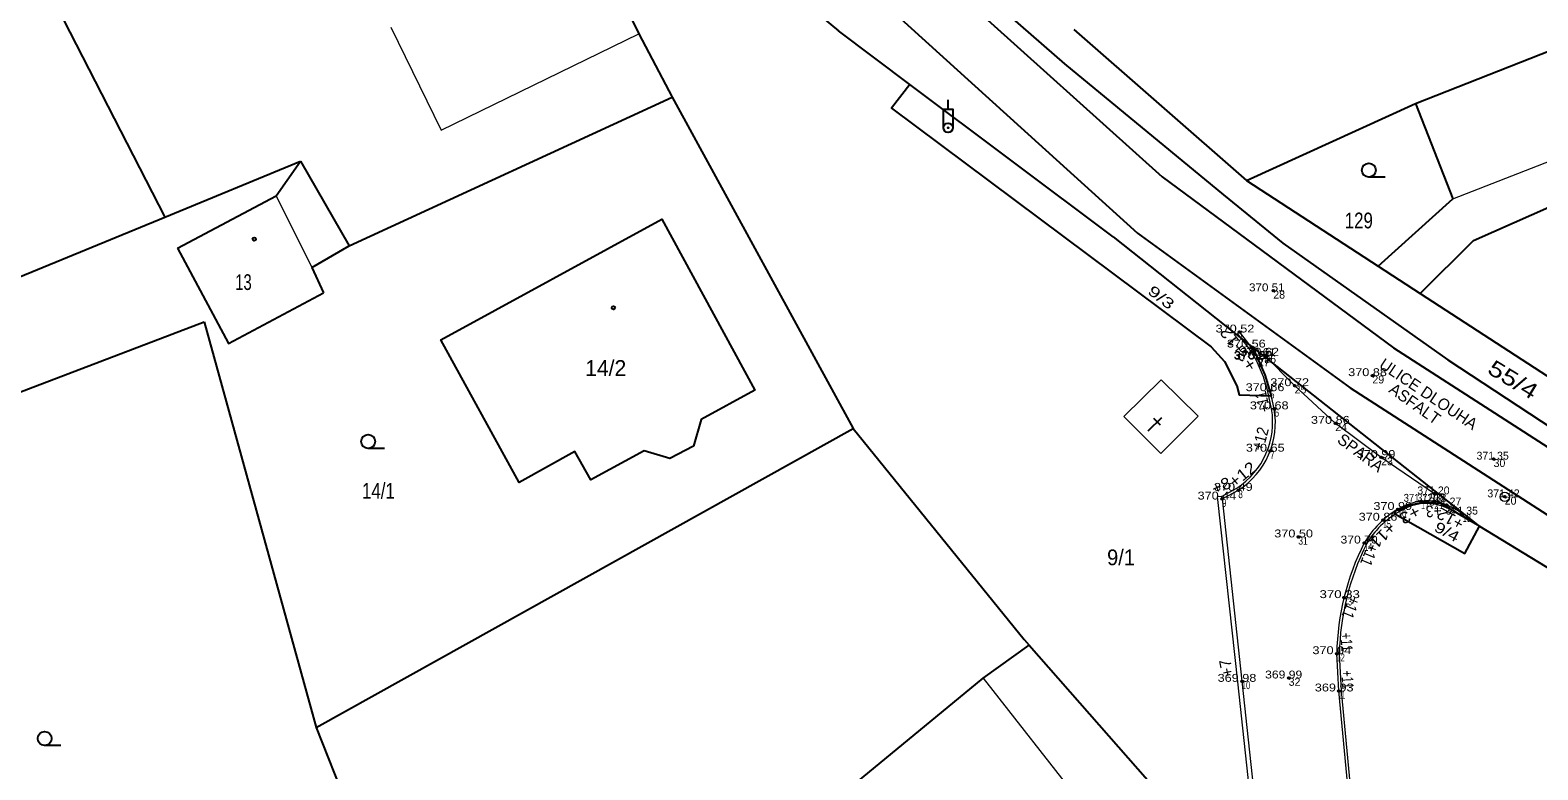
# Model space of a CAD drawing. Extents: x -592965 to -592390, y -1145071 to -1144631.
# Drawn here: x -592701.3 to -592620.1, y -1144793.9 to -1144754 of the extents above; entities that cross this region are included whole.
import ezdxf
from ezdxf.enums import TextEntityAlignment as Align

# ---------------------------------------------------------------- set-up
doc = ezdxf.new("R2010")
doc.units = 0
doc.header["$LTSCALE"] = 0.17
doc.header["$PDMODE"] = 32
doc.header["$PDSIZE"] = 0.085
for name, color, linetype, lineweight in [('1', 7, 'Continuous', 13), ('3', 7, 'Continuous', 13), ('4', 7, 'Continuous', 25)]:
    doc.layers.add(name, color=color, linetype=linetype, lineweight=lineweight)
doc.layers.add('2', color=7, linetype='Continuous')

msp = doc.modelspace()

# ---------------------------------------------------------------- linework, layer by layer
at = {"layer": '1'}
for p, q in [((-592635.5, -1144771.07), (-592636.13, -1144770.26)), ((-592635.61, -1144771.15), (-592635.5, -1144771.07)), ((-592634.48, -1144773.42), (-592634.61, -1144773.46)), ((-592634.4, -1144774.41), (-592634.61, -1144773.46)), ((-592634.26, -1144774.4), (-592634.48, -1144773.42)), ((-592634.26, -1144774.4), (-592634.4, -1144774.41)), ((-592637.09, -1144779.12), (-592637.33, -1144779.15)), ((-592637.33, -1144779.15), (-592637.31, -1144779.29)), ((-592637.07, -1144779.26), (-592636.19, -1144778.79)), ((-592627.6, -1144779.82), (-592627.53, -1144779.95)), ((-592624.97, -1144779.58), (-592625.03, -1144779.71)), ((-592628.4, -1144780.4), (-592628.3, -1144780.5)), ((-592624.1, -1144780.07), (-592624.18, -1144780.18))]:
    msp.add_line(p, q, dxfattribs=at)
for points in [[(-592635.43, -1144771.44), (-592635.61, -1144771.15), (-592636.24, -1144770.35), (-592636.13, -1144770.26)], [(-592625.64, -1144779.38), (-592625.62, -1144778.98), (-592628.5, -1144777.02), (-592630.97, -1144775.18), (-592633.16, -1144773.15), (-592634.79, -1144771.51), (-592635.14, -1144771.68)], [(-592637.07, -1144779.26), (-592637.09, -1144779.12), (-592636.28, -1144778.68)], [(-592637.31, -1144779.29), (-592636.24, -1144789.11), (-592635.14, -1144799.25)], [(-592637.07, -1144779.26), (-592636, -1144789.08), (-592634.9, -1144799.22)], [(-592629.52, -1144802.71), (-592629.9, -1144798.92), (-592630.78, -1144789.6), (-592630.89, -1144787.59)], [(-592629.38, -1144802.7), (-592629.76, -1144798.91), (-592630.64, -1144789.59), (-592630.75, -1144787.6)]]:
    msp.add_lwpolyline(points, dxfattribs=at)
msp.add_circle((-592621.84, -1144779.14), 0.25, dxfattribs=at)
for centre, radius, start, end in [((-592640.1575, -1144774.2299), 5.6283, 26.93992, 34.15522), ((-592641.5166, -1144775.0872), 7.0957, 13.25738, 30.93109), ((-592643.1786, -1144775.7243), 8.9986, 14.83708, 26.70742), ((-592638.6054, -1144775.1073), 4.2628, 303.05919, 9.41484), ((-592638.5399, -1144775.1376), 4.343, 302.75725, 9.77875), ((-592625.0473, -1144784.1827), 5.0547, 120.33284, 149.66716), ((-592625.1307, -1144784.1231), 4.8137, 119.89707, 149.77646), ((-592625.995, -1144782.3841), 3.025, 83.26049, 122.04462), ((-592625.995, -1144782.3443), 2.8441, 83.23556, 122.66415), ((-592626.4518, -1144783.285), 3.8474, 53.80834, 78.12308), ((-592626.3924, -1144783.1229), 3.8178, 53.09689, 78.6334), ((-592617.2255, -1144787.8194), 13.6664, 153.07049, 179.03805), ((-592617.083, -1144787.8514), 13.6693, 153.25553, 178.94635)]:
    msp.add_arc(centre, radius, start, end, dxfattribs=at)
at = {"layer": '2'}
for p in [(-592634.31, -1144768.04), (-592636.13, -1144770.26), (-592635.5, -1144771.07), (-592635.14, -1144771.68), (-592635.12, -1144771.72), (-592634.79, -1144771.51), (-592634.78, -1144771.53), (-592628.97, -1144772.61), (-592634.48, -1144773.42), (-592633.16, -1144773.15), (-592634.26, -1144774.4), (-592630.97, -1144775.18), (-592634.48, -1144776.68), (-592628.5, -1144777.02), (-592622.44, -1144777.11), (-592637.07, -1144779.26), (-592636.19, -1144778.79), (-592625.62, -1144778.98), (-592621.84, -1144779.14), (-592627.6, -1144779.82), (-592626.35, -1144779.38), (-592625.64, -1144779.38), (-592624.97, -1144779.58), (-592624.1, -1144780.07), (-592628.4, -1144780.4), (-592632.96, -1144781.3), (-592629.41, -1144781.63), (-592630.5, -1144784.57), (-592630.89, -1144787.59), (-592633.48, -1144788.9), (-592636, -1144789.08), (-592630.78, -1144789.6)]:
    msp.add_point(p, dxfattribs=at)
at = {"layer": '3'}
for centre, radius in [((-592634.3101, -1144768.0399), 0.0625), ((-592634.3101, -1144768.0399), 0.0395), ((-592634.3101, -1144768.0399), 0.0125), ((-592636.1301, -1144770.2599), 0.0625), ((-592636.1301, -1144770.2599), 0.0395), ((-592636.1301, -1144770.2599), 0.0125), ((-592635.5001, -1144771.0699), 0.0625), ((-592635.5001, -1144771.0699), 0.0395), ((-592635.5001, -1144771.0699), 0.0125), ((-592635.1401, -1144771.6799), 0.0625), ((-592635.1201, -1144771.7199), 0.0625), ((-592635.1401, -1144771.6799), 0.0395), ((-592635.1201, -1144771.7199), 0.0395), ((-592635.1401, -1144771.6799), 0.0125), ((-592635.1201, -1144771.7199), 0.0125), ((-592634.7901, -1144771.5099), 0.0625), ((-592634.7801, -1144771.5299), 0.0625), ((-592634.7901, -1144771.5099), 0.0395), ((-592634.7801, -1144771.5299), 0.0395), ((-592634.7901, -1144771.5099), 0.0125), ((-592634.7801, -1144771.5299), 0.0125), ((-592628.9701, -1144772.6099), 0.0625), ((-592628.9701, -1144772.6099), 0.0395), ((-592628.9701, -1144772.6099), 0.0125), ((-592634.4801, -1144773.4199), 0.0625), ((-592634.4801, -1144773.4199), 0.0395), ((-592634.4801, -1144773.4199), 0.0125), ((-592633.1601, -1144773.1499), 0.0625), ((-592633.1601, -1144773.1499), 0.0395), ((-592633.1601, -1144773.1499), 0.0125), ((-592634.2601, -1144774.3999), 0.0625), ((-592634.2601, -1144774.3999), 0.0395), ((-592634.2601, -1144774.3999), 0.0125), ((-592630.9701, -1144775.1799), 0.0625), ((-592630.9701, -1144775.1799), 0.0395), ((-592630.9701, -1144775.1799), 0.0125), ((-592634.4801, -1144776.6799), 0.0625), ((-592634.4801, -1144776.6799), 0.0395), ((-592634.4801, -1144776.6799), 0.0125), ((-592628.5001, -1144777.0199), 0.0625), ((-592628.5001, -1144777.0199), 0.0395), ((-592628.5001, -1144777.0199), 0.0125), ((-592622.4401, -1144777.1099), 0.0625), ((-592622.4401, -1144777.1099), 0.0395), ((-592622.4401, -1144777.1099), 0.0125), ((-592637.0701, -1144779.2599), 0.0625), ((-592637.0701, -1144779.2599), 0.0395), ((-592637.0701, -1144779.2599), 0.0125), ((-592636.1901, -1144778.7899), 0.0625), ((-592636.1901, -1144778.7899), 0.0395), ((-592636.1901, -1144778.7899), 0.0125), ((-592625.6201, -1144778.9799), 0.0625), ((-592625.6201, -1144778.9799), 0.0395), ((-592625.6201, -1144778.9799), 0.0125), ((-592621.8401, -1144779.1399), 0.0625), ((-592621.8401, -1144779.1399), 0.0395), ((-592621.8401, -1144779.1399), 0.0125), ((-592627.6001, -1144779.8199), 0.0625), ((-592627.6001, -1144779.8199), 0.0395), ((-592627.6001, -1144779.8199), 0.0125), ((-592626.3501, -1144779.3799), 0.0625), ((-592626.3501, -1144779.3799), 0.0395), ((-592626.3501, -1144779.3799), 0.0125), ((-592625.6401, -1144779.3799), 0.0625), ((-592625.6401, -1144779.3799), 0.0395), ((-592625.6401, -1144779.3799), 0.0125), ((-592624.9701, -1144779.5799), 0.0625), ((-592624.9701, -1144779.5799), 0.0395), ((-592624.9701, -1144779.5799), 0.0125), ((-592624.1001, -1144780.0699), 0.0625), ((-592624.1001, -1144780.0699), 0.0395), ((-592624.1001, -1144780.0699), 0.0125), ((-592628.4001, -1144780.3999), 0.0625), ((-592628.4001, -1144780.3999), 0.0395), ((-592628.4001, -1144780.3999), 0.0125), ((-592632.9601, -1144781.2999), 0.0625), ((-592632.9601, -1144781.2999), 0.0395), ((-592632.9601, -1144781.2999), 0.0125), ((-592629.4101, -1144781.6299), 0.0625), ((-592629.4101, -1144781.6299), 0.0395), ((-592629.4101, -1144781.6299), 0.0125), ((-592630.5001, -1144784.5699), 0.0625), ((-592630.5001, -1144784.5699), 0.0395), ((-592630.5001, -1144784.5699), 0.0125), ((-592630.8901, -1144787.5899), 0.0625), ((-592630.8901, -1144787.5899), 0.0395), ((-592630.8901, -1144787.5899), 0.0125), ((-592633.4801, -1144788.8999), 0.0625), ((-592633.4801, -1144788.8999), 0.0395), ((-592633.4801, -1144788.8999), 0.0125), ((-592636.0001, -1144789.0799), 0.0625), ((-592636.0001, -1144789.0799), 0.0395), ((-592636.0001, -1144789.0799), 0.0125), ((-592630.7801, -1144789.5999), 0.0625), ((-592630.7801, -1144789.5999), 0.0395), ((-592630.7801, -1144789.5999), 0.0125)]:
    msp.add_circle(centre, radius, dxfattribs=at)
at = {"layer": '4'}
for p, q in [((-592653.84, -1144748.59), (-592645.55, -1144755.81)), ((-592653.76, -1144749.79), (-592640.29, -1144761.91)), ((-592626.64, -1144757.96), (-592607.41, -1144750.36)), ((-592656.05, -1144751.86), (-592641.63, -1144764.93)), ((-592699.48, -1144753.44), (-592694.03, -1144764.07)), ((-592645.05, -1144753.97), (-592635.75, -1144762.1)), ((-592668.48, -1144754.19), (-592666.7, -1144757.61)), ((-592645.55, -1144755.81), (-592637, -1144762.87)), ((-592684.09, -1144765.62), (-592666.7, -1144757.61)), ((-592666.7, -1144757.61), (-592656.95, -1144775.47)), ((-592651.83, -1144758.26), (-592651.83, -1144757.76)), ((-592635.75, -1144762.1), (-592626.64, -1144757.96)), ((-592626.64, -1144757.96), (-592624.63, -1144763.09)), ((-592623.53, -1144765.34), (-592606.96, -1144757.99)), ((-592688.03, -1144762.93), (-592686.72, -1144761.06)), ((-592686.72, -1144761.06), (-592684.09, -1144765.62)), ((-592640.29, -1144761.91), (-592627.84, -1144771.11)), ((-592635.75, -1144762.1), (-592628.65, -1144766.72)), ((-592628.285, -1144761.92), (-592629.16, -1144761.92)), ((-592693.35, -1144765.74), (-592688.03, -1144762.93)), ((-592637, -1144762.87), (-592633.79, -1144765.48)), ((-592628.65, -1144766.72), (-592624.63, -1144763.09)), ((-592641.63, -1144764.93), (-592630.17, -1144773.28)), ((-592626.39, -1144768.19), (-592623.53, -1144765.34)), ((-592693.35, -1144765.74), (-592691.3, -1144769.57)), ((-592686.11, -1144766.79), (-592684.09, -1144765.62)), ((-592633.79, -1144765.48), (-592624.9, -1144771.77)), ((-592686.11, -1144766.79), (-592685.48, -1144768.15)), ((-592628.65, -1144766.72), (-592626.39, -1144768.19)), ((-592626.39, -1144768.19), (-592616.23, -1144774.8)), ((-592724.27, -1144782.05), (-592691.9, -1144769.72)), ((-592627.84, -1144771.11), (-592589.96, -1144795.52)), ((-592624.9, -1144771.77), (-592618.62, -1144775.89)), ((-592630.17, -1144773.28), (-592589.61, -1144799.37)), ((-592641.05, -1144775.58), (-592640.322, -1144774.865)), ((-592640.386, -1144775.285), (-592640.744, -1144774.922)), ((-592656.95, -1144775.47), (-592647.73, -1144786.83)), ((-592682.195, -1144776.54), (-592683.07, -1144776.54)), ((-592649.93, -1144788.92), (-592647.46, -1144787.13)), ((-592657.67, -1144795.29), (-592649.93, -1144788.92)), ((-592685.87, -1144791.57), (-592681.2, -1144803.34)), ((-592699.625, -1144792.54), (-592700.5, -1144792.54))]:
    msp.add_line(p, q, dxfattribs=at)
at = {"layer": '4', "lineweight": 13}
for p, q in [((-592681.85, -1144753.84), (-592679.14, -1144759.39)), ((-592679.14, -1144759.39), (-592668.48, -1144754.19)), ((-592624.63, -1144763.09), (-592605.19, -1144755.48)), ((-592688.03, -1144762.93), (-592686.11, -1144766.79)), ((-592642.36, -1144774.82), (-592640.35, -1144772.84)), ((-592640.35, -1144772.84), (-592638.35, -1144774.8)), ((-592642.36, -1144774.82), (-592640.37, -1144776.81)), ((-592640.37, -1144776.81), (-592638.35, -1144774.8)), ((-592649.93, -1144788.92), (-592638.07, -1144804.05))]:
    msp.add_line(p, q, dxfattribs=at)
at = {"layer": '4'}
for points in [[(-592678.44, -1144732.7), (-592676.29, -1144738.2), (-592668.48, -1144754.19)], [(-592664.73, -1144748.23), (-592663.97, -1144748.86), (-592657.74, -1144754.03)], [(-592642.94, -1144765.13), (-592653.89, -1144756.92), (-592657.74, -1144754.03)], [(-592653.89, -1144756.92), (-592654.87, -1144758.2), (-592637.65, -1144771.07), (-592636.93, -1144771.86), (-592636.27, -1144773.17), (-592636.14, -1144773.64), (-592634.41, -1144773.7), (-592634.75, -1144772.57), (-592635.39, -1144771.11)], [(-592652.08, -1144759.26), (-592652.08, -1144758.26), (-592651.58, -1144758.26), (-592651.58, -1144759.26)], [(-592726.72, -1144777.51), (-592694.03, -1144764.07), (-592686.72, -1144761.06)], [(-592642.94, -1144765.13), (-592635.39, -1144771.11), (-592623.31, -1144780.66), (-592623.2, -1144780.73), (-592617.69, -1144784.09)], [(-592691.3, -1144769.57), (-592690.6, -1144770.88), (-592685.48, -1144768.15)], [(-592691.9, -1144769.72), (-592685.87, -1144791.57), (-592656.95, -1144775.47)], [(-592627.78, -1144779.92), (-592626.98, -1144779.59), (-592626.22, -1144779.43), (-592625.31, -1144779.48), (-592623.31, -1144780.66)], [(-592627.78, -1144779.92), (-592627.73, -1144780.07), (-592623.99, -1144782.19), (-592623.2, -1144780.73)], [(-592647.73, -1144786.83), (-592647.46, -1144787.13), (-592635.1, -1144801.2)]]:
    msp.add_lwpolyline(points, dxfattribs=at)
msp.add_lwpolyline([(-592665.54, -1144776.41), (-592666.81, -1144777.07), (-592668.21, -1144776.66), (-592671.08, -1144778.22), (-592671.94, -1144776.7), (-592674.93, -1144778.38), (-592679.15, -1144770.68), (-592667.25, -1144764.19), (-592662.24, -1144773.4), (-592665.13, -1144774.97)], close=True, dxfattribs=at)
for centre, radius in [((-592651.83, -1144759.26), 0.25), ((-592651.83, -1144759.26), 0.025), ((-592629.16, -1144761.545), 0.375), ((-592689.21, -1144765.26), 0.0875), ((-592669.86, -1144768.96), 0.0875), ((-592683.07, -1144776.165), 0.375), ((-592700.5, -1144792.165), 0.375)]:
    msp.add_circle(centre, radius, dxfattribs=at)

# ---------------------------------------------------------------- texts
at = {"layer": '1'}
for s, rotation, width, p in [('+12', 127.875, 1.15, (-592636.2537, -1144770.5488)), ('+3', 122.8, 1.25, (-592635.4783, -1144771.6234)), ('+11', 102.804, 0.8, (-592634.5935, -1144773.9517)), ('+12', 75.155, 0.9, (-592634.6996, -1144776.0994)), ('+12', 39.063, 1.15, (-592635.7789, -1144778.1813)), ('+8', 22.973, 1.1, (-592636.998, -1144778.8239)), ('+3', 207.051, 1.2, (-592627.092, -1144779.8464)), ('+3', 182.632, 0.9, (-592625.6788, -1144779.6115)), ('+12', 151.06, 1.05, (-592624.6205, -1144780.0653)), ('+11', 225, 1.1, (-592628.6288, -1144781.0008)), ('+11', 247.584, 0.85, (-592629.4154, -1144782.1603)), ('+11', 247.584, 0.85, (-592630.4054, -1144784.9903)), ('+11', 273.164, 0.7, (-592630.6682, -1144786.9849)), ('+11', 273.164, 0.7, (-592630.6182, -1144789.0049))]:
    msp.add_text(s, height=0.62, rotation=rotation, dxfattribs=dict(at, width=width)).set_placement(p, align=Align.CENTER)
for s, rotation, p in [('ULICE DLOUHA', 326.083, (-592626.1195, -1144773.8636)), ('ASFALT', 324.567, (-592626.8597, -1144774.3813)), ('SPARA', 323.316, (-592629.7897, -1144777.0172)), ('+7', 101.437, (-592636.5388, -1144788.3065))]:
    msp.add_text(s, height=0.62, rotation=rotation, dxfattribs=at).set_placement(p, align=Align.CENTER)
at = {"layer": '2'}
for s, p in [('28', (-592634.31, -1144768.465)), ('27', (-592635.14, -1144772.105)), ('26', (-592634.79, -1144771.935)), ('29', (-592628.97, -1144773.035)), ('25', (-592633.16, -1144773.575)), ('24', (-592630.97, -1144775.605)), ('23', (-592628.5, -1144777.445)), ('30', (-592622.44, -1144777.535)), ('22', (-592625.62, -1144779.405)), ('20', (-592621.84, -1144779.565)), ('32', (-592633.48, -1144789.325))]:
    msp.add_text(s, height=0.425, dxfattribs=at).set_placement(p)
for s, width, p in [('1', 0.45, (-592636.13, -1144770.685)), ('2', 0.75, (-592635.5, -1144771.495)), ('3', 0.75, (-592635.12, -1144772.145)), ('4', 0.75, (-592634.78, -1144771.955)), ('5', 0.75, (-592634.48, -1144773.845)), ('6', 0.85, (-592634.26, -1144774.825)), ('7', 0.75, (-592634.48, -1144777.105)), ('8', 0.75, (-592636.19, -1144779.215)), ('9', 0.75, (-592637.07, -1144779.685)), ('16', 0.65, (-592627.6, -1144780.245)), ('17', 0.6, (-592626.35, -1144779.805)), ('21', 0.8, (-592625.64, -1144779.805)), ('18', 0.6, (-592624.97, -1144780.005)), ('15', 0.6, (-592628.4, -1144780.825)), ('19', 0.6, (-592624.1, -1144780.495)), ('31', 0.8, (-592632.96, -1144781.725)), ('14', 0.6, (-592629.41, -1144782.055)), ('13', 0.6, (-592630.5, -1144784.995)), ('12', 0.6, (-592630.89, -1144788.015)), ('10', 0.65, (-592636, -1144789.505)), ('11', 0.45, (-592630.78, -1144790.025))]:
    msp.add_text(s, height=0.425, dxfattribs=dict(at, width=width)).set_placement(p)
at = {"layer": '3'}
for s, width, p in [('370 51', 1.1, (-592634.6585, -1144768.07)), ('370 52', 1.2, (-592636.373, -1144770.29)), ('370 56', 1.2, (-592635.7615, -1144771.1)), ('370 62', 1.2, (-592635.0445, -1144771.54)), ('370 62', 1.2, (-592635.3945, -1144771.71)), ('370 60', 1.2, (-592635.3865, -1144771.75)), ('370 61', 1.1, (-592635.14, -1144771.56)), ('370 72', 1.2, (-592633.425, -1144773.18)), ('370 88', 1.2, (-592629.2315, -1144772.64)), ('370 66', 1.2, (-592634.753, -1144773.45)), ('370 68', 1.2, (-592634.528, -1144774.43)), ('370 86', 1.2, (-592631.2365, -1144775.21)), ('370 65', 1.2, (-592634.7415, -1144776.71)), ('370 99', 1.2, (-592628.773, -1144777.05)), ('370 49', 1.2, (-592636.463, -1144778.82)), ('370 44', 1.2, (-592637.343, -1144779.29)), ('371 12', 0.9, (-592626.504, -1144779.41)), ('371 18', 0.85, (-592625.8075, -1144779.41)), ('370 86', 1.2, (-592628.6665, -1144780.43)), ('370 99', 1.2, (-592627.873, -1144779.85)), ('370 50', 1.2, (-592633.2145, -1144781.33)), ('370 70', 1.15, (-592629.6865, -1144781.66)), ('370 33', 1.25, (-592630.7295, -1144784.6)), ('370 04', 1.2, (-592631.1565, -1144787.62)), ('369 98', 1.2, (-592636.2645, -1144789.11)), ('369 99', 1.15, (-592633.7495, -1144788.93)), ('369 93', 1.2, (-592631.0275, -1144789.63))]:
    msp.add_text(s, height=0.425, dxfattribs=dict(at, width=width)).set_placement(p, align=Align.CENTER)
for s, p in [('371 35', (-592622.492, -1144777.14)), ('371 20', (-592625.6805, -1144779.01)), ('371 27', (-592625.047, -1144779.61)), ('371 42', (-592621.907, -1144779.17)), ('371 35', (-592624.152, -1144780.1))]:
    msp.add_text(s, height=0.425, dxfattribs=at).set_placement(p, align=Align.CENTER)
at = {"layer": '4'}
for s, width, p in [('129', 0.8, (-592630.46, -1144764.68)), ('13', 0.7, (-592690.23, -1144768)), ('14/1', 0.8, (-592683.403, -1144779.245)), ('9/1', 0.95, (-592643.263, -1144782.83))]:
    msp.add_text(s, height=0.85, dxfattribs=dict(at, width=width)).set_placement(p)
for s, height, rotation, width, p in [('9/3', 0.57, 322.125, 1.45, (-592641.127, -1144768.153)), ('55/4', 0.85, 328.625, 1.3, (-592622.84, -1144772.441)), ('9/4', 0.57, 332.166, 1.3, (-592625.694, -1144780.958))]:
    msp.add_text(s, height=height, rotation=rotation, dxfattribs=dict(at, width=width)).set_placement(p)
msp.add_text('14/2', height=0.85, dxfattribs=at).set_placement((-592671.379, -1144772.63))

doc.saveas('drawing.dxf')
